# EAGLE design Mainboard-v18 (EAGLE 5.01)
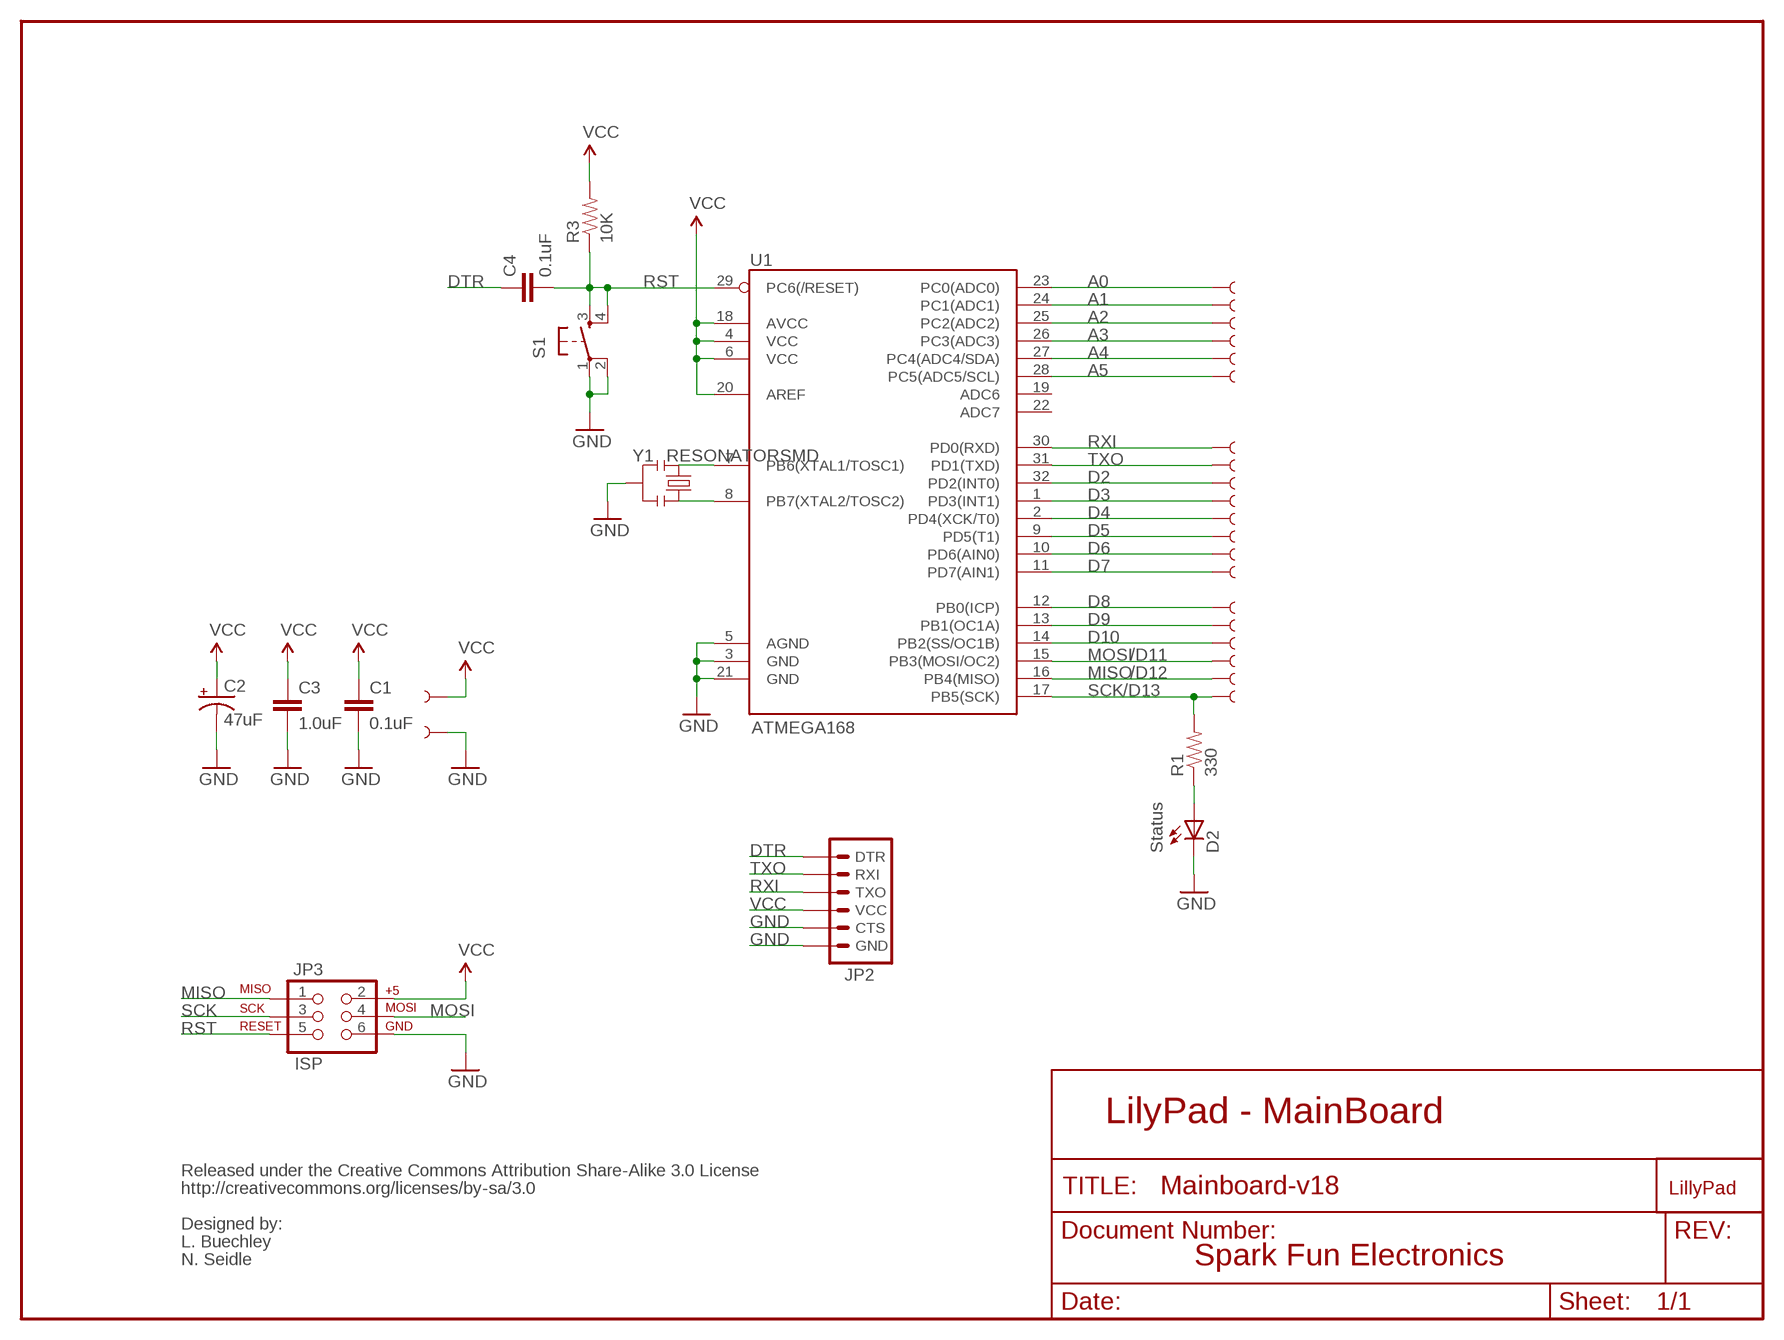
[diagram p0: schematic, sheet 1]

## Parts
C1  0.1uF  CAP0603  [0603]
C2  47uF  CAP_POL3528  [EIA3528]
C3  1.0uF  CAP0603  [0603]
C4  0.1uF  CAP0603  [0603]
D2  Status  LED0603  [LED-0603]
GND  SEWTAP1  [SEWTAP]
JP2  ARDUINO_SERIAL_PROGRAMSMD  [1X06-SMD]
JP3  ISP  AVR_SPI_PRG_6NS  [2X3-NS]
R1  330  RESISTOR0603  [0603]
R3  10K  RESISTOR0603  [0603]
S1  TAC_SWITCHSMD  [TACTILE_SWITCH_SMD]
U1  ATMEGA168  [TQFP32-08]
U$1  LOGO-LPLPA  [LOGO-LPA]
U$4  SEWTAP1  [SEWTAP]
U$30  SEWTAP1  [SEWTAP]
U$31  SEWTAP1  [SEWTAP]
U$32  SEWTAP1  [SEWTAP]
U$33  SEWTAP1  [SEWTAP]
U$34  SEWTAP1  [SEWTAP]
U$35  SEWTAP1  [SEWTAP]
U$36  SEWTAP1  [SEWTAP]
U$37  SEWTAP1  [SEWTAP]
U$38  SEWTAP1  [SEWTAP]
U$39  SEWTAP1  [SEWTAP]
U$40  SEWTAP1  [SEWTAP]
U$41  SEWTAP1  [SEWTAP]
U$42  SEWTAP1  [SEWTAP]
U$43  SEWTAP1  [SEWTAP]
U$44  SEWTAP1  [SEWTAP]
U$45  SEWTAP1  [SEWTAP]
U$46  SEWTAP1  [SEWTAP]
U$47  SEWTAP1  [SEWTAP]
U$48  SEWTAP1  [SEWTAP]
U$51  SEWTAP1  [SEWTAP]
Y1  RESONATORSMD  [RESONATOR-SMD]

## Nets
A0: U1.23(PC0(ADC0)) U$4.1
A1: U1.24(PC1(ADC1)) U$30.1
A2: U1.25(PC2(ADC2)) U$31.1
A3: U1.26(PC3(ADC3)) U$32.1
A4: U1.27(PC4(ADC4/SDA)) U$33.1
A5: U1.28(PC5(ADC5/SCL)) U$34.1
D2: U1.32(PD2(INT0)) U$45.1
D3: U1.1(PD3(INT1)) U$44.1
D4: U1.2(PD4(XCK/T0)) U$43.1
D5: U1.9(PD5(T1)) U$42.1
D6: U1.10(PD6(AIN0)) U$41.1
D7: U1.11(PD7(AIN1)) U$48.1
D8: U1.12(PB0(ICP)) U$35.1
D9: U1.13(PB1(OC1A)) U$36.1
D10: U1.14(PB2(SS/OC1B)) U$37.1
DTR: C4.1 JP2.1(DTR)
GND [VCC]: C1.2 C2.C(-) C3.2 D2.C GND.1 JP2.5(CTS) JP2.6(GND) JP3.6 S1.1 S1.2 U1.3(GND) U1.5(AGND) U1.21(GND) Y1.2
MISO: JP3.1 U1.16(PB4(MISO)) U$39.1
MOSI: JP3.4 U1.15(PB3(MOSI/OC2)) U$38.1
N$1: U1.7(PB6(XTAL1/TOSC1)) Y1.1
N$2: D2.A R1.1
N$3: U1.8(PB7(XTAL2/TOSC2)) Y1.3
RST: C4.2 JP3.5 R3.1 S1.3 S1.4 U1.29(PC6(/RESET))
RXI: JP2.3(TXO) U1.30(PD0(RXD)) U$47.1
SCK: JP3.3 R1.2 U1.17(PB5(SCK)) U$40.1
TXO: JP2.2(RXI) U1.31(PD1(TXD)) U$46.1
VCC [VCC]: C1.1 C2.A(+) C3.1 JP2.4(VCC) JP3.2 R3.2 U1.4(VCC) U1.6(VCC) U1.18(AVCC) U1.20(AREF) U$51.1
Unconnected: U1.19(ADC6) U1.22(ADC7)

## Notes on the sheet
- /D11
- /D12
- /D13
- LilyPad - MainBoard
- Released under the Creative Commons Attribution Share-Alike 3.0 License
- http://creativecommons.org/licenses/by-sa/3.0
- Designed by:
- L. Buechley
- N. Seidle | Spark Fun Electronics

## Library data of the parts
C1 C3 C4 = SparkFun:CAP: Capacitor
C2 = SparkFun:CAP_POL: Capacitor Polarized
D2 = SparkFun:LED: LEDs
GND U$4 U$30-U$48 U$51 = LilyPad-Wearables:SEWTAP
JP2 = SparkFun:ARDUINO_SERIAL_PROGRAM
JP3 = SparkFun:AVR_SPI_PRG_6: AVR ISP 6 Pin This is the reduced ISP connector for AVR programming. Common on Arduino. This footprint will take up less PCB space and can be used with a 10-pin to 6-pin adapter such as SKU: BOB-08508
R1 R3 = SparkFun:RESISTOR: Resistor
S1 = SparkFun:TAC_SWITCH: Momentary Switch Button commonly used for reset or general input. Spark Fun Electronics SKU : COM-00097
U1 = SparkFun:ATMEGA168
U$1 = LilyPad-Wearables:LOGO-LP
Y1 = SparkFun:RESONATOR: Resonator Small SMD resonator. This is the itty bitty 10/20MHz resonators with built in caps. CSTCE10M0G55 and CSTCE20M0V53. Footprint has been reviewed closely but hasn't been tested yet.

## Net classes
0 Default: width 0.203 mm
1 VCC: width 0.305 mm

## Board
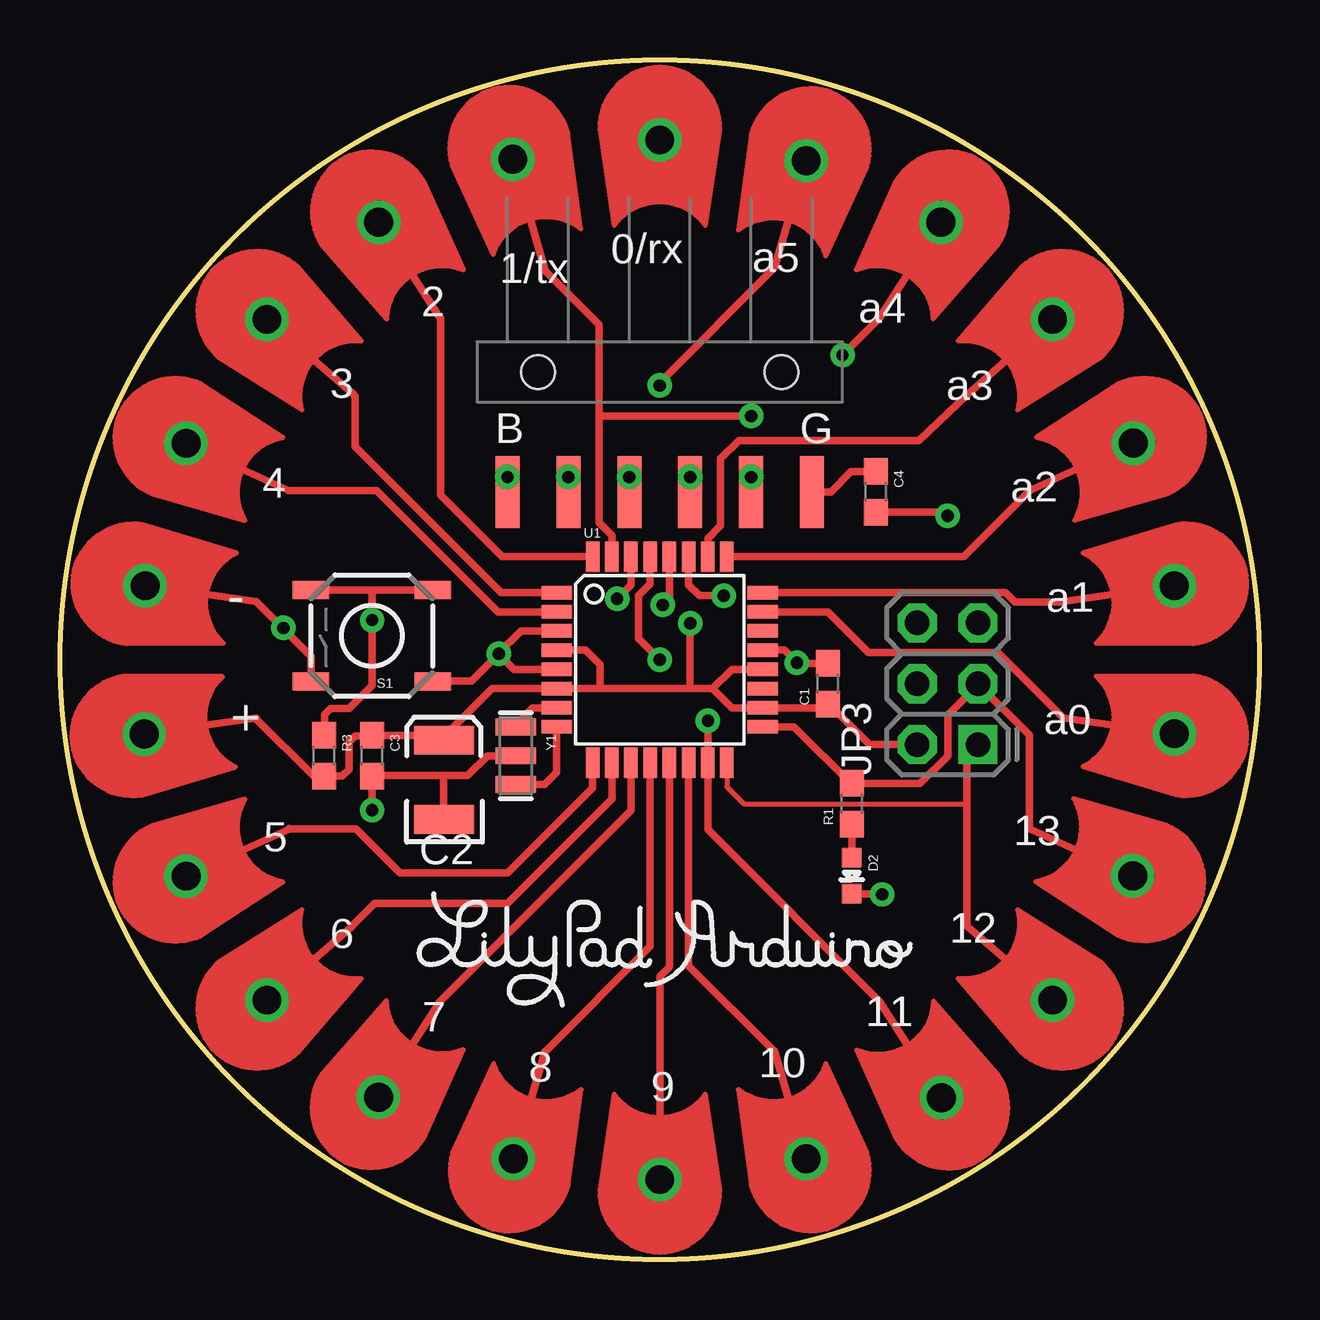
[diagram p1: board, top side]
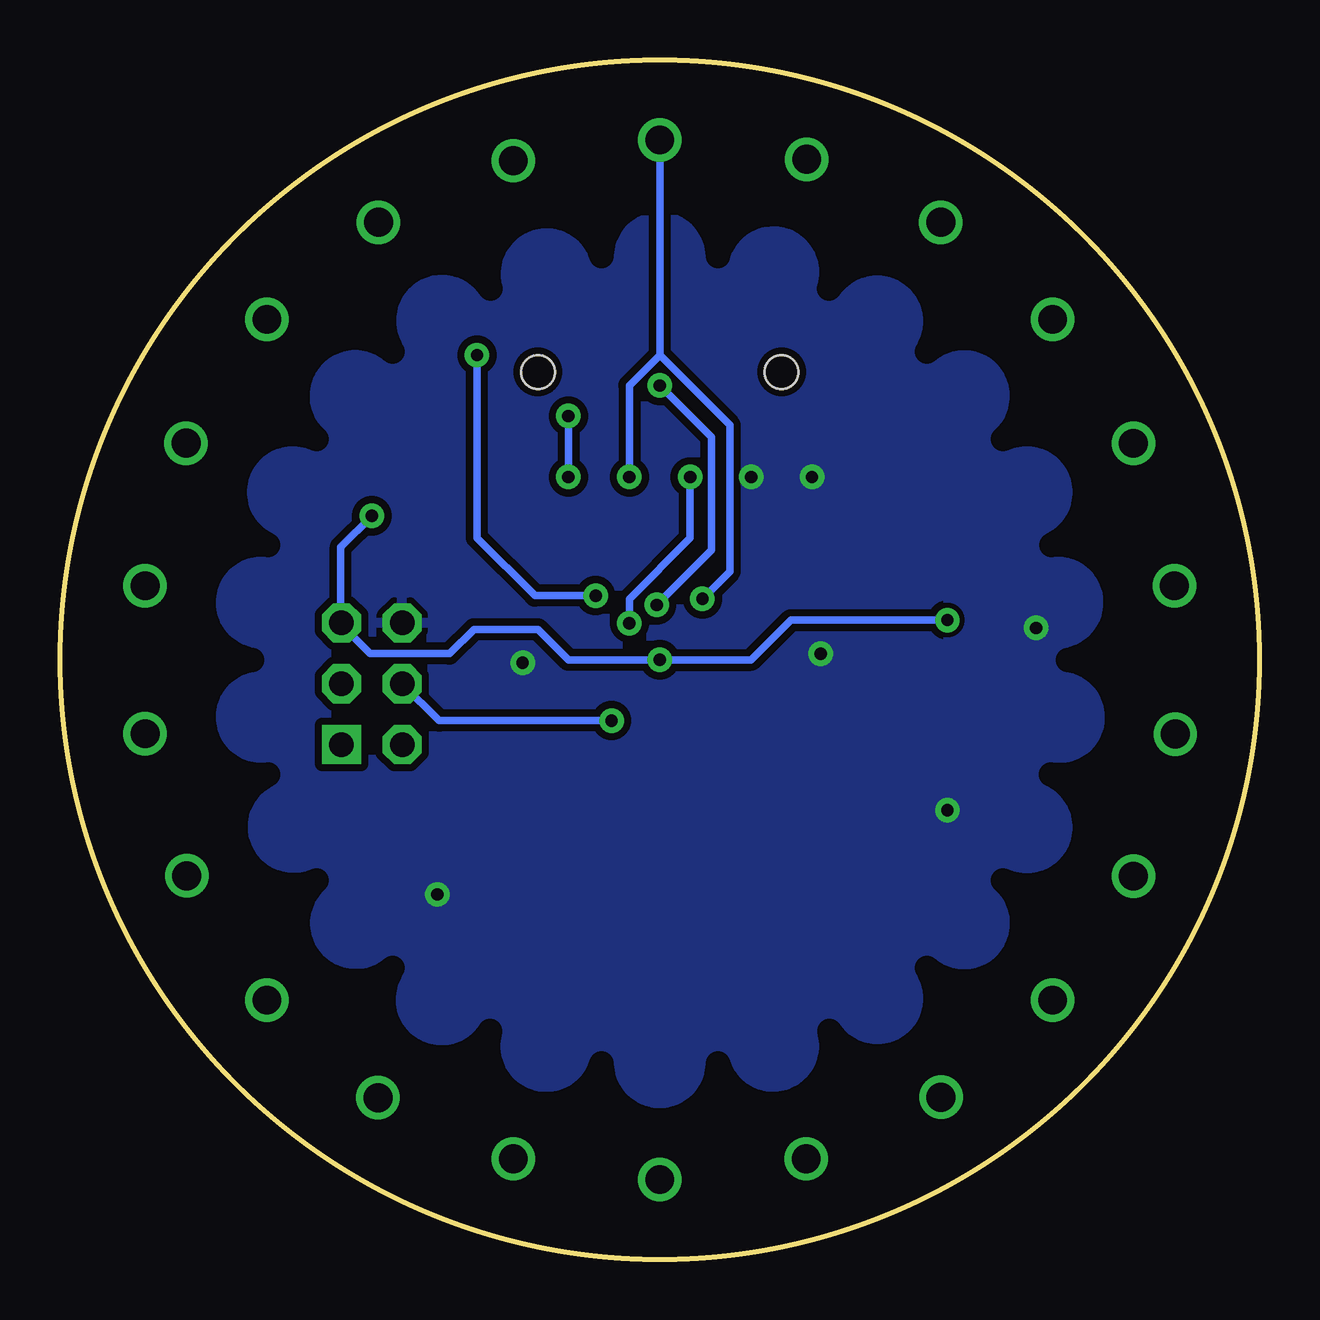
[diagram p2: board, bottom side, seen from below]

Size 50 x 50 mm. Coordinates in mm from the lower left corner, seen from the top.
Outline: circle at 25,25 radius 25
Copper layers (1*16): Top 0.035mm / dielectric 1.5mm / Bottom 0.035mm
Design rules "SparkFun": minimum track width 8mil, minimum drill 20mil, track to track 8mil, track to pad 8mil, pad to pad 8mil, via to via 8mil, smd to smd 8mil, copper to edge 10mil, drill to drill 8mil, minimum pad ring 12mil, minimum via ring 10mil, stop-mask expansion 4mil, vias tented up to drill 20mil, thermal gap 10mil
bRestrict: area 2.4,2.4 to 47.6,47.6; area 21,42.8 to 23.5,44; area 31.6,41.3 to 34.4,43; area 36.3,38.4 to 38.9,40.7; area 40,34.1 to 42,36.9; area 42.2,29.2 to 43.6,31.8; area 42.8,23.9 to 44,26.2; area 42.2,18.2 to 43.7,20.9; area 36.3,9.4 to 39,11.7; area 31.7,7 to 34.5,8.7; area 26.5,6 to 28.9,7.3; area 21.1,6 to 23.6,7.3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; 22 lines

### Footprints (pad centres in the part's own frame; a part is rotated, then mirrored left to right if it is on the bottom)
0603 = smd 1.1 x 1: 1 -0.85,0; 2 0.85,0
EIA3528 = smd 1.2 x 2.5: A 1.65,0; C -1.65,0
LED-0603 = smd 0.8 x 0.8: A 0,-0.75; C 0,0.75
SEWTAP = drill 1.2 round: 1 0.03,0
1X06-SMD = smd 1 x 3: 1 -6.35,5; 2 -3.81,5; 3 -1.27,5; 4 1.27,5; 5 3.81,5; 6 6.35,5 | hole 1.4: -5.08,0; 5.08,0
2X3-NS = drill 1.016 square: 1 -2.54,-1.27 | drill 1.016 octagon: 2 -2.54,1.27; 3 0,-1.27; 4 0,1.27; 5 2.54,-1.27; 6 2.54,1.27
TACTILE_SWITCH_SMD = smd 1.524 x 0.762: 1 -2.54,1.905; 2 2.54,1.905; 3 -2.54,-1.905; 4 2.54,-1.905
TQFP32-08 = smd 1.27 x 0.559: 1 -4.293,2.8; 2 -4.293,2; 3 -4.293,1.2; 4 -4.293,0.4; 5 -4.293,-0.4; 6 -4.293,-1.2; 7 -4.293,-2; 8 -4.293,-2.8; 17 4.293,-2.8; 18 4.293,-2; 19 4.293,-1.2; 20 4.293,-0.4; 21 4.293,0.4; 22 4.293,1.2; 23 4.293,2; 24 4.293,2.8 | smd 0.559 x 1.27: 9 -2.8,-4.293; 10 -2,-4.293; 11 -1.2,-4.293; 12 -0.4,-4.293; 13 0.4,-4.293; 14 1.2,-4.293; 15 2,-4.293; 16 2.8,-4.293; 25 2.8,4.293; 26 2,4.293; 27 1.2,4.293; 28 0.4,4.293; 29 -0.4,4.293; 30 -1.2,4.293; 31 -2,4.293; 32 -2.8,4.293
RESONATOR-SMD = smd 0.7 x 1.7: 1 -1.2,0; 2 0,0; 3 1.2,0

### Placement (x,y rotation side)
C1  32,24 90 top
C2  16,20 90 top
C3  13,21 270 top
C4  34,32 270 top
D2  33,16 180 top
GND  3.52,28.09 351.8 top
JP2  25,37 180 top
JP3  37,24 90 top
R1  33,19 90 top
R3  11,21 270 top
S1  13,26 180 top
U1  25,25 0 top
U$1  25,13.3 0 top
U$4  46.48,21.91 171.8 top
U$30  46.48,28.09 188.2 top
U$31  44.77,34.04 204.5 top
U$32  41.4,39.21 220.9 top
U$33  36.74,43.26 237.3 top
U$34  31.11,45.83 253.7 top
U$35  18.89,4.17 73.7 top
U$36  25,3.3 90 top
U$37  31.11,4.17 106.3 top
U$38  36.76,6.72 122.7 top
U$39  41.4,10.79 139.1 top
U$40  44.74,15.98 155.5 top
U$41  8.6,10.79 40.9 top
U$42  5.23,15.97 24.5 top
U$43  5.23,34.03 335.5 top
U$44  8.6,39.21 319.1 top
U$45  13.27,43.26 302.7 top
U$46  18.87,45.89 286.3 top
U$47  25,46.7 270 top
U$48  13.26,6.74 57.3 top
U$51  3.48,21.9 8.2 top
Y1  19,21 270 top

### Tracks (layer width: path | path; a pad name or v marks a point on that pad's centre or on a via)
A0
  Top 0.305: U$4.1 41.83,22.58 41.82,22.58 39.1,25.3 33.7,25.3 32,27 U1.23
A1
  Top 0.305: U$30.1 41.83,27.42 41.82,27.42 41.8,27.4 39.8,27.4 39.4,27.8 U1.24
A2
  Top 0.305: U$31.1 40.5,32.1 40.5,32.11 40.49,32.11 37.67,29.29 U1.25
A3
  Top 0.305: U1.26 27,30.05 27.54,30.59 27.54,33.38 28.3,34.14 35.8,34.14 37.83,36.05 U$32.1
A4  (via drill 0.51)
  Top 0.305: U$33.1 34.2,39.3 34.2,39.28 v32.62,37.7 | U1.27 26.2,28.12 26.65,27.67 v27.67,27.67
  Bottom 0.305: v27.67,27.67 30.21,27.67 32.62,30.08 v32.62,37.7
A5  (via drill 0.51)
  Top 0.305: U$34.1 29.8,41.4 29.8,41.36 25,36.56 v25,36.43 | U1.28 25.4,27.56 v25.13,27.29
  Bottom 0.305: v25,36.43 22.84,34.27 22.84,29.57 v25.13,27.29
D2
  Top 0.305: U$45.1 15.8,39.3 15.86,39.24 15.86,31.86 18.42,29.29 U1.32
D3
  Top 0.305: U$44.1 12.16,36.13 12.17,36.13 12.3,36 12.3,33.89 18.39,27.8 U1.1
D4
  Top 0.305: U$43.1 9.54,32.06 9.56,32.06 13.19,32.06 18.25,27 U1.2
D5
  Top 0.305: U$42.1 9.54,17.93 9.54,17.95 9.56,17.96 9.58,17.94 12.35,17.94 14.18,16.11 18.65,16.11 22.2,19.66 U1.9
D6
  Top 0.305: U$41.1 12.15,13.87 12.15,13.88 13.11,14.84 18.65,14.84 23,19.19 U1.10
D7
  Top 0.305: U$48.1 15.8,10.7 15.8,10.72 23.8,18.72 U1.11
D8
  Top 0.305: U$35.1 20.21,8.68 20.24,8.68 24.6,13.04 U1.12
D9
  Top 0.305: 25,11.79 U$36.1 | 25,11.79 25,8 | U1.13 25.4,12.19 25,11.79
D10
  Top 0.305: U$37.1 29.79,8.69 29.75,8.69 26.2,12.24 U1.14
DTR
  Top 0.305: JP2.1 32.13,32 32.98,32.85 C4.1
GND  (via drill 0.51)
  Top 0.305: GND.1 8.17,27.42 8.18,27.42 9.27,26.33 v9.31,26.33 9.31,26.31 9.3,26.3 10.46,25.14 S1.2 | 32,24.8 C1.2 30.74,24.85 v30.71,24.87 30.19,25.4 U1.21 | S1.1 15.57,24.09 15.58,24.09 15.6,24.11 17.15,24.11 v18.29,25.25 | v13.01,18.73 v13,18.74 C3.2 13.04,20.15 13.06,20.17 15.98,20.17 | C2.C 16,18.41 16.03,18.45 15.98,18.5 15.98,20.17 | U1.3 19.21,26.2 18.27,25.25 | v18.29,25.25 18.32,25.28 | D2.C 34.24,15.25 v34.27,15.22 | Y1.2 17.82,21 17,20.17 15.98,20.17 | 18.27,25.25 v18.29,25.25 | U1.5 18.92,24.6 18.27,25.25 | JP2.6 v18.65,32.62 | JP2.5 v21.19,32.62
  pour Bottom (isolate 0.305): -1,51 51,51 51,-1 -1,-1
  pour Bottom: 8,29 13,29 13,25 10,25 8,27
MISO
  Top 0.203: U1.16 27.8,19.7 28.5,19 37.8,19
  Top 0.305: U$39.1 37.85,13.87 37.82,13.9 37.8,13.9 37.8,19 37.8,20.99 JP3.1
MOSI  (via drill 0.51)
  Top 0.305: U$38.1 34.2,10.7 34.2,10.72 27,17.92 U1.15 v27,22.45 v27.01,22.46
  Bottom 0.305: JP3.4 35.74,24.01 | JP3.4 | v27.01,22.46 34.2,22.46 JP3.4
N$1
  Top 0.305: Y1.1 19,22.3 19.7,23 U1.7
N$2
  Top 0.305: 33,16.7 D2.A R1.1
N$3
  Top 0.305: U1.8 20.71,20.31 20.2,19.8 19.3,19.8 19.2,19.7 19.1,19.8 Y1.3
RST  (via drill 0.51)
  Top 0.305: 15.56,27.91 S1.3 | 13.01,27.91 15.56,27.91 | 13.01,27.91 S1.4 | 15.56,27.91 15.6,27.95 | 13.01,27.91 v13.01,26.65 13.01,23.93 12.05,22.97 11.28,22.97 11.03,22.71 11.03,21.82 R3.1 | C4.2 36.85,31.15 v37,31 | U1.29 24.6,28.16 24.11,27.67 24.11,25.89 v25,25
  Bottom 0.305: v37,31 38.3,29.7 38.3,26.6 38.27,26.57 JP3.5 38.32,26.54 38.34,26.52 37.06,25.25 33.76,25.25 32.75,26.27 30.08,26.27 28.81,25 v25,25 21.19,25 19.54,26.65 v13.01,26.65 12.94,26.65
RXI  (via drill 0.51)
  Top 0.254: 26.27,31.98 JP2.3 v26.27,32.62
  Top 0.305: U1.30 23.8,28.12 v23.22,27.54
  Bottom 0.305: 25,37.7 U$47.1 | v26.27,32.62 26.27,36.43 25,37.7 | v23.22,27.54 22.08,28.68 22.08,34.78 25,37.7
SCK
  Top 0.305: U$40.1 40.46,17.93 40.4,17.99 40.4,21.87 JP3.3 38.3,24 37,22.7 37,21 35.85,19.85 R1.2 33,19.8 30.6,22.2 U1.17
TXO  (via drill 0.51)
  Top 0.254: 28.81,31.98 JP2.2 v28.81,32.62
  Top 0.305: U1.31 23,30.18 22.46,30.71 22.46,35.16 | 22.46,35.16 22.46,38.97 20.2,41.23 20.2,41.3 U$46.1 | 22.46,35.16 25,35.16 v28.81,35.16
  Bottom 0.305: v28.81,35.16 v28.81,32.62
VCC  (via drill 0.51)
  Top 0.305: U$51.1 8.17,22.58 8.17,22.57 8.16,22.56 10.57,20.15 R3.2 11.77,20.15 12.05,20.43 12.05,21.57 12.3,21.82 12.94,21.82 12.96,21.85 C3.1 15.7,21.85 15.91,21.65 C2.A 15.95,21.65 15.9,21.7 18,23.8 U1.6 22.5,23.8 | U1.20 28,24.6 27.2,23.8 | 26.27,23.8 22.5,23.8 | 26.27,23.8 27.2,23.8 | 27.2,23.8 28,23 U1.18 31.9,23 32,23.1 C1.1 32.05,23.15 33.74,21.46 JP3.2 | U1.4 21.9,25.4 22.5,24.8 22.5,23.8 | v26.27,26.52 26.27,23.8 | v23.73,32.62 JP2.4
  Bottom 0.305: v26.27,26.52 26.27,27.54 23.73,30.08 v23.73,32.62

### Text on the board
tPlace: L. Buechley | N. Seidle | 0/rx | 1/tx | a5 | 2 | a4 | 3 | a3 | B | G | 4 | a2 | - | a1 | + | a0 | 5 | 13 | 6 | 12 | 11 | 7 | 10 | 8 | 9 | Released under the Creative Commons Attribution Share-Alike 3.0 License | http://creativecommons.org/licenses/by-sa/3.0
